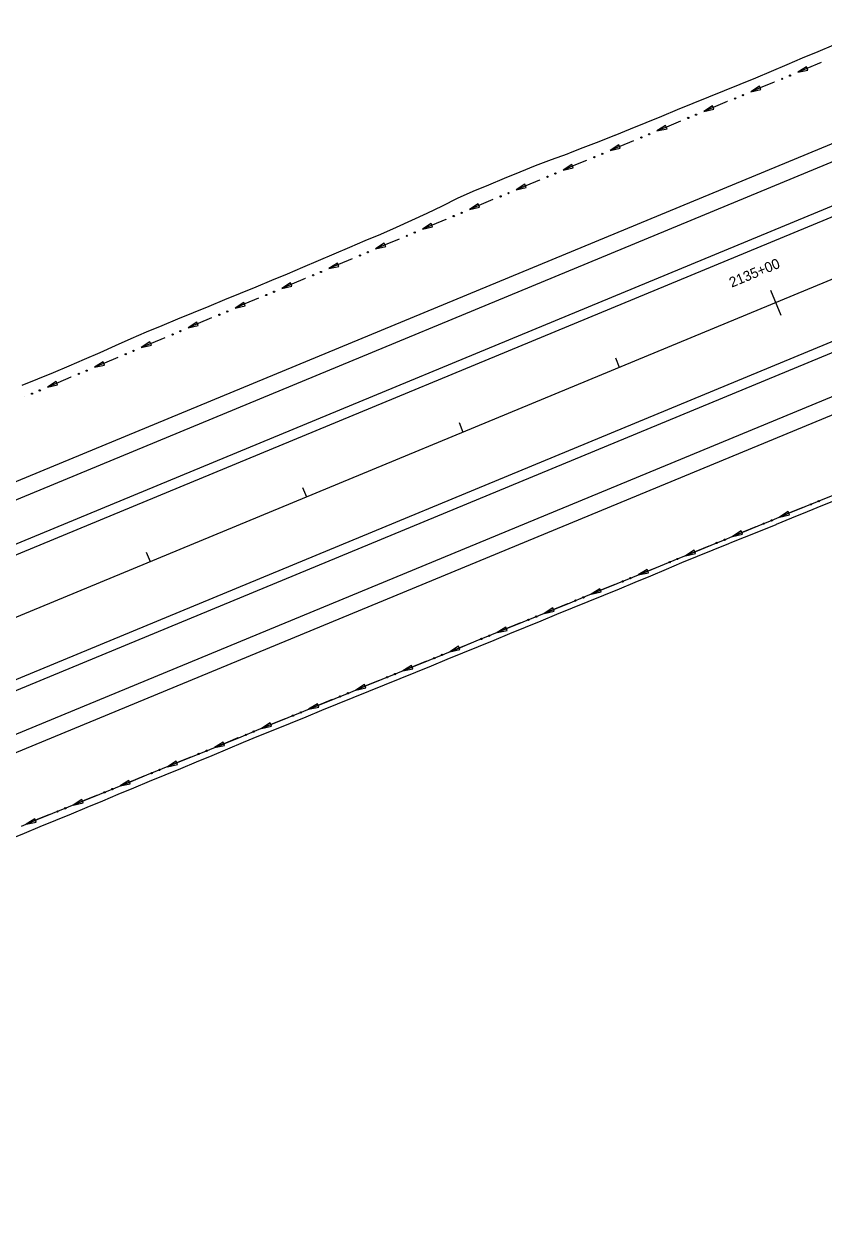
# Model space of a CAD drawing. Extents: x 1611108 to 1749517, y 619561 to 797725.
# Drawn here: x 1719028 to 1719500, y 766660 to 767372 of the extents above; entities that cross this region are included whole.
import ezdxf

# ---------------------------------------------------------------- set-up
doc = ezdxf.new("R2010")
doc.units = 0
for name, color, linetype in [('R_Ditch', 7, 'Continuous'), ('R_Horz Alg', 7, 'Continuous'), ('R_Horz Alg Stationing', 7, 'Continuous'), ('R_Proposed Const Limits', 7, 'Continuous'), ('R_Proposed Road', 7, 'Continuous')]:
    doc.layers.add(name, color=color, linetype=linetype)

msp = doc.modelspace()

# ---------------------------------------------------------------- linework, layer by layer
at = {"layer": 'R_Ditch'}
for p, q in [((1719489.75, 767346.92), (1719484.62, 767343.64)), ((1719490.56, 767344.96), (1719489.75, 767346.92)), ((1719484.62, 767343.64), (1719490.56, 767344.96)), ((1719462.02, 767335.38), (1719456.88, 767332.1)), ((1719456.88, 767332.1), (1719462.83, 767333.43)), ((1719462.83, 767333.43), (1719462.02, 767335.38)), ((1719434.29, 767323.83), (1719429.16, 767320.55)), ((1719429.16, 767320.55), (1719435.1, 767321.88)), ((1719435.1, 767321.88), (1719434.29, 767323.83)), ((1719406.56, 767312.27), (1719401.43, 767308.98)), ((1719407.38, 767310.32), (1719406.56, 767312.27)), ((1719401.43, 767308.98), (1719407.38, 767310.32)), ((1719378.85, 767300.69), (1719373.72, 767297.4)), ((1719373.72, 767297.4), (1719379.66, 767298.74)), ((1719379.66, 767298.74), (1719378.85, 767300.69)), ((1719351.14, 767289.09), (1719346.01, 767285.8)), ((1719346.01, 767285.8), (1719351.95, 767287.14)), ((1719351.95, 767287.14), (1719351.14, 767289.09)), ((1719323.43, 767277.49), (1719318.31, 767274.19)), ((1719318.31, 767274.19), (1719324.25, 767275.53)), ((1719324.25, 767275.53), (1719323.43, 767277.49)), ((1719295.73, 767265.86), (1719290.61, 767262.56)), ((1719290.61, 767262.56), (1719296.55, 767263.91)), ((1719296.55, 767263.91), (1719295.73, 767265.86)), ((1719268.04, 767254.22), (1719262.92, 767250.92)), ((1719268.86, 767252.27), (1719268.04, 767254.22)), ((1719262.92, 767250.92), (1719268.86, 767252.27)), ((1719240.36, 767242.57), (1719235.24, 767239.26)), ((1719235.24, 767239.26), (1719241.18, 767240.62)), ((1719241.18, 767240.62), (1719240.36, 767242.57)), ((1719212.67, 767230.91), (1719207.55, 767227.6)), ((1719207.55, 767227.6), (1719213.49, 767228.96)), ((1719213.49, 767228.96), (1719212.67, 767230.91)), ((1719184.99, 767219.25), (1719179.87, 767215.94)), ((1719185.81, 767217.3), (1719184.99, 767219.25)), ((1719179.87, 767215.94), (1719185.81, 767217.3)), ((1719157.31, 767207.58), (1719152.19, 767204.28)), ((1719152.19, 767204.28), (1719158.13, 767205.63)), ((1719158.13, 767205.63), (1719157.31, 767207.58)), ((1719129.63, 767195.92), (1719124.51, 767192.62)), ((1719124.51, 767192.62), (1719130.45, 767193.97)), ((1719130.45, 767193.97), (1719129.63, 767195.92)), ((1719101.95, 767184.26), (1719096.83, 767180.96)), ((1719102.77, 767182.31), (1719101.95, 767184.26)), ((1719096.83, 767180.96), (1719102.77, 767182.31)), ((1719074.26, 767172.6), (1719069.14, 767169.3)), ((1719069.14, 767169.3), (1719075.08, 767170.65)), ((1719075.08, 767170.65), (1719074.26, 767172.6)), ((1719046.58, 767160.94), (1719041.46, 767157.63)), ((1719041.46, 767157.63), (1719047.4, 767158.99)), ((1719047.4, 767158.99), (1719046.58, 767160.94)), ((1719478.94, 767083.98), (1719473.79, 767080.72)), ((1719479.74, 767082.02), (1719478.94, 767083.98)), ((1719473.79, 767080.72), (1719479.74, 767082.02)), ((1719451.15, 767072.58), (1719446, 767069.33)), ((1719446, 767069.33), (1719451.95, 767070.62)), ((1719451.95, 767070.62), (1719451.15, 767072.58)), ((1719423.35, 767061.2), (1719418.2, 767057.94)), ((1719418.2, 767057.94), (1719424.15, 767059.24)), ((1719424.15, 767059.24), (1719423.35, 767061.2)), ((1719395.55, 767049.83), (1719390.39, 767046.58)), ((1719390.39, 767046.58), (1719396.35, 767047.87)), ((1719396.35, 767047.87), (1719395.55, 767049.83)), ((1719367.74, 767038.47), (1719362.58, 767035.22)), ((1719362.58, 767035.22), (1719368.54, 767036.51)), ((1719368.54, 767036.51), (1719367.74, 767038.47)), ((1719339.93, 767027.13), (1719334.77, 767023.89)), ((1719340.72, 767025.17), (1719339.93, 767027.13)), ((1719334.77, 767023.89), (1719340.72, 767025.17)), ((1719312.11, 767015.8), (1719306.95, 767012.56)), ((1719306.95, 767012.56), (1719312.9, 767013.84)), ((1719312.9, 767013.84), (1719312.11, 767015.8)), ((1719284.29, 767004.47), (1719279.13, 767001.23)), ((1719279.13, 767001.23), (1719285.08, 767002.51)), ((1719285.08, 767002.51), (1719284.29, 767004.47)), ((1719256.47, 766993.14), (1719251.31, 766989.9)), ((1719251.31, 766989.9), (1719257.26, 766991.18)), ((1719257.26, 766991.18), (1719256.47, 766993.14)), ((1719228.65, 766981.82), (1719223.49, 766978.57)), ((1719223.49, 766978.57), (1719229.44, 766979.86)), ((1719229.44, 766979.86), (1719228.65, 766981.82)), ((1719200.83, 766970.49), (1719195.67, 766967.24)), ((1719201.62, 766968.53), (1719200.83, 766970.49)), ((1719195.67, 766967.24), (1719201.62, 766968.53)), ((1719173.01, 766959.16), (1719167.85, 766955.92)), ((1719167.85, 766955.92), (1719173.8, 766957.2)), ((1719173.8, 766957.2), (1719173.01, 766959.16)), ((1719145.19, 766947.83), (1719140.03, 766944.59)), ((1719145.98, 766945.87), (1719145.19, 766947.83)), ((1719140.03, 766944.59), (1719145.98, 766945.87)), ((1719117.37, 766936.5), (1719112.21, 766933.26)), ((1719112.21, 766933.26), (1719118.16, 766934.54)), ((1719118.16, 766934.54), (1719117.37, 766936.5)), ((1719089.55, 766925.17), (1719084.39, 766921.93)), ((1719084.39, 766921.93), (1719090.34, 766923.21)), ((1719090.34, 766923.21), (1719089.55, 766925.17)), ((1719061.73, 766913.84), (1719056.57, 766910.6)), ((1719062.52, 766911.89), (1719061.73, 766913.84)), ((1719056.57, 766910.6), (1719062.52, 766911.89)), ((1719033.91, 766902.52), (1719028.75, 766899.27)), ((1719028.75, 766899.27), (1719034.7, 766900.56)), ((1719034.7, 766900.56), (1719033.91, 766902.52))]:
    msp.add_line(p, q, dxfattribs=at)
for points in [[(1719498.47, 767349.39), (1719490.06, 767345.9), (1719484.62, 767343.64)], [(1719498.5, 767349.41), (1719498.47, 767349.39)], [(1719470.73, 767337.86), (1719462.36, 767334.38), (1719456.88, 767332.1)], [(1719470.77, 767337.88), (1719470.73, 767337.86)], [(1719443, 767326.32), (1719434.67, 767322.84), (1719429.16, 767320.55)], [(1719443.04, 767326.33), (1719443, 767326.32)], [(1719415.28, 767314.76), (1719406.98, 767311.3), (1719401.43, 767308.98)], [(1719415.31, 767314.77), (1719415.28, 767314.76)], [(1719387.56, 767303.18), (1719379.55, 767299.84), (1719379.3, 767299.73), (1719373.72, 767297.4)], [(1719387.59, 767303.2), (1719387.56, 767303.18)], [(1719359.85, 767291.59), (1719353.3, 767288.86), (1719351.62, 767288.15), (1719346.01, 767285.8)], [(1719359.88, 767291.61), (1719359.85, 767291.59)], [(1719332.14, 767279.99), (1719323.95, 767276.56), (1719318.31, 767274.19)], [(1719332.18, 767280), (1719332.14, 767279.99)], [(1719304.44, 767268.37), (1719296.29, 767264.95), (1719290.61, 767262.56)], [(1719304.48, 767268.39), (1719304.44, 767268.37)], [(1719276.75, 767256.74), (1719268.63, 767253.32), (1719262.92, 767250.92)], [(1719276.78, 767256.75), (1719276.75, 767256.74)], [(1719249.06, 767245.09), (1719240.98, 767241.68), (1719235.24, 767239.26)], [(1719249.1, 767245.1), (1719249.06, 767245.09)], [(1719221.38, 767233.43), (1719213.34, 767230.04), (1719207.55, 767227.6)], [(1719221.41, 767233.44), (1719221.38, 767233.43)], [(1719193.7, 767221.76), (1719185.69, 767218.39), (1719179.87, 767215.94)], [(1719193.73, 767221.78), (1719193.7, 767221.76)], [(1719166.01, 767210.1), (1719158.04, 767206.74), (1719152.19, 767204.28)], [(1719166.05, 767210.12), (1719166.01, 767210.1)], [(1719138.33, 767198.44), (1719130.39, 767195.1), (1719124.51, 767192.62)], [(1719138.37, 767198.46), (1719138.33, 767198.44)], [(1719110.65, 767186.78), (1719102.75, 767183.45), (1719096.83, 767180.96)], [(1719110.68, 767186.8), (1719110.65, 767186.78)], [(1719082.97, 767175.12), (1719075.1, 767171.8), (1719069.14, 767169.3)], [(1719083, 767175.13), (1719082.97, 767175.12)], [(1719055.29, 767163.46), (1719047.45, 767160.16), (1719041.46, 767157.63)], [(1719055.32, 767163.47), (1719055.29, 767163.46)], [(1719027.64, 767151.81), (1719027.6, 767151.8)], [(1719026.08, 766898.19), (1719035.34, 766901.96), (1719044.6, 766905.73), (1719053.86, 766909.5), (1719063.12, 766913.27), (1719072.38, 766917.04), (1719081.65, 766920.81), (1719090.91, 766924.59), (1719100.17, 766928.36), (1719109.43, 766932.13), (1719118.69, 766935.9), (1719127.96, 766939.67), (1719137.22, 766943.44), (1719146.48, 766947.21), (1719155.74, 766950.98), (1719165, 766954.76), (1719174.26, 766958.53), (1719183.53, 766962.3), (1719192.79, 766966.07), (1719202.05, 766969.84), (1719211.31, 766973.61), (1719220.57, 766977.39), (1719229.83, 766981.16), (1719239.1, 766984.93), (1719248.36, 766988.7), (1719257.62, 766992.47), (1719266.88, 766996.24), (1719276.14, 767000.01), (1719285.41, 767003.79), (1719294.67, 767007.56), (1719303.93, 767011.33), (1719313.19, 767015.1), (1719322.45, 767018.87), (1719331.71, 767022.64), (1719340.98, 767026.41), (1719350.24, 767030.19), (1719359.5, 767033.96), (1719368.76, 767037.74), (1719378.01, 767041.52), (1719387.27, 767045.3), (1719396.53, 767049.08), (1719405.79, 767052.87), (1719415.04, 767056.65), (1719424.3, 767060.44), (1719433.55, 767064.23), (1719442.8, 767068.02), (1719444.49, 767068.71), (1719452.06, 767071.81), (1719461.31, 767075.6), (1719470.56, 767079.4), (1719470.81, 767079.5), (1719479.81, 767083.2), (1719489.06, 767087), (1719498.31, 767090.8), (1719507.56, 767094.6)], [(1719487.66, 767086.42), (1719479.81, 767083.2), (1719473.79, 767080.72)], [(1719487.7, 767086.44), (1719487.66, 767086.42)], [(1719459.88, 767075.02), (1719452.06, 767071.81), (1719446, 767069.33)], [(1719459.91, 767075.03), (1719459.88, 767075.02)], [(1719432.08, 767063.63), (1719424.3, 767060.44), (1719418.2, 767057.94)], [(1719432.12, 767063.64), (1719432.08, 767063.63)], [(1719404.28, 767052.25), (1719396.53, 767049.08), (1719390.39, 767046.58)], [(1719404.32, 767052.26), (1719404.28, 767052.25)], [(1719376.47, 767040.89), (1719368.76, 767037.74), (1719362.58, 767035.22)], [(1719376.51, 767040.91), (1719376.47, 767040.89)], [(1719348.66, 767029.55), (1719340.98, 767026.41), (1719334.77, 767023.89)], [(1719348.69, 767029.56), (1719348.66, 767029.55)], [(1719320.84, 767018.21), (1719313.19, 767015.1), (1719306.95, 767012.56)], [(1719320.88, 767018.23), (1719320.84, 767018.21)], [(1719293.02, 767006.89), (1719285.41, 767003.79), (1719279.13, 767001.23)], [(1719293.06, 767006.9), (1719293.02, 767006.89)], [(1719265.2, 766995.56), (1719257.62, 766992.47), (1719251.31, 766989.9)], [(1719265.24, 766995.57), (1719265.2, 766995.56)], [(1719237.38, 766984.23), (1719229.83, 766981.16), (1719223.49, 766978.57)], [(1719237.42, 766984.24), (1719237.38, 766984.23)], [(1719209.56, 766972.9), (1719202.05, 766969.84), (1719195.67, 766967.24)], [(1719209.6, 766972.92), (1719209.56, 766972.9)], [(1719181.74, 766961.57), (1719174.26, 766958.53), (1719167.85, 766955.92)], [(1719181.78, 766961.59), (1719181.74, 766961.57)], [(1719153.92, 766950.24), (1719146.48, 766947.21), (1719140.03, 766944.59)], [(1719153.96, 766950.26), (1719153.92, 766950.24)], [(1719126.1, 766938.92), (1719118.69, 766935.9), (1719112.21, 766933.26)], [(1719126.14, 766938.93), (1719126.1, 766938.92)], [(1719098.28, 766927.59), (1719090.91, 766924.59), (1719084.39, 766921.93)], [(1719098.32, 766927.6), (1719098.28, 766927.59)], [(1719070.46, 766916.26), (1719063.12, 766913.27), (1719056.57, 766910.6)], [(1719070.5, 766916.27), (1719070.46, 766916.26)], [(1719042.64, 766904.93), (1719035.34, 766901.96), (1719028.75, 766899.27)], [(1719042.68, 766904.95), (1719042.64, 766904.93)]]:
    msp.add_lwpolyline(points, dxfattribs=at)
for centre in [(1719475.38, 767339.76), (1719480.01, 767341.68), (1719447.65, 767328.22), (1719452.28, 767330.14), (1719424.55, 767318.59), (1719419.93, 767316.66), (1719392.21, 767305.09), (1719396.83, 767307.02), (1719364.49, 767293.5), (1719369.11, 767295.43), (1719336.79, 767281.9), (1719341.41, 767283.83), (1719309.09, 767270.28), (1719313.71, 767272.22), (1719286.01, 767260.59), (1719281.39, 767258.65), (1719253.7, 767247), (1719258.32, 767248.95), (1719226.02, 767235.34), (1719230.64, 767237.29), (1719202.96, 767225.63), (1719198.34, 767223.68), (1719170.66, 767212.02), (1719175.27, 767213.96), (1719142.97, 767200.36), (1719147.59, 767202.3), (1719119.91, 767190.64), (1719115.29, 767188.7), (1719087.61, 767177.04), (1719092.23, 767178.98), (1719059.93, 767165.37), (1719064.55, 767167.32), (1719032.25, 767153.71), (1719036.86, 767155.66), (1719496.96, 767090.2), (1719492.32, 767088.3), (1719464.54, 767076.89), (1719469.17, 767078.79), (1719436.74, 767065.5), (1719441.38, 767067.4), (1719408.94, 767054.12), (1719413.58, 767056.01), (1719381.14, 767042.76), (1719385.77, 767044.65), (1719357.96, 767033.3), (1719353.32, 767031.41), (1719325.51, 767020.08), (1719330.15, 767021.96), (1719297.69, 767008.75), (1719302.33, 767010.64), (1719269.87, 766997.42), (1719274.51, 766999.31), (1719242.05, 766986.09), (1719246.69, 766987.98), (1719218.87, 766976.65), (1719214.23, 766974.76), (1719186.41, 766963.43), (1719191.05, 766965.32), (1719158.59, 766952.1), (1719163.23, 766953.99), (1719130.77, 766940.78), (1719135.41, 766942.67), (1719102.95, 766929.45), (1719107.59, 766931.34), (1719079.77, 766920.01), (1719075.13, 766918.12), (1719047.31, 766906.79), (1719051.95, 766908.68)]:
    msp.add_circle(centre, 0.375, dxfattribs=at)
at = {"layer": 'R_Horz Alg'}
msp.add_line((1715964.86, 765755.05), (1723860.62, 769025.58), dxfattribs=at)
at = {"layer": 'R_Horz Alg Stationing'}
for points in [[(1719468.52, 767214.98), (1719474.65, 767200.2)], [(1719376.9, 767174.86), (1719379.2, 767169.32)], [(1719284.51, 767136.59), (1719286.81, 767131.05)], [(1719192.13, 767098.32), (1719194.42, 767092.78)], [(1719099.74, 767060.06), (1719102.03, 767054.51)]]:
    msp.add_lwpolyline(points, dxfattribs=at)
at = {"layer": 'R_Proposed Const Limits'}
for points in [[(1719026.41, 767158.69), (1719035.67, 767162.47), (1719044.92, 767166.26), (1719054.13, 767170.16), (1719063.32, 767174.1), (1719072.51, 767178.05), (1719081.62, 767182.19), (1719090.77, 767186.22), (1719099.95, 767190.2), (1719109.17, 767194.08), (1719118.4, 767197.93), (1719127.65, 767201.72), (1719136.91, 767205.51), (1719146.16, 767209.29), (1719155.4, 767213.12), (1719164.64, 767216.95), (1719173.87, 767220.79), (1719183.11, 767224.62), (1719192.34, 767228.46), (1719201.54, 767232.39), (1719210.74, 767236.31), (1719219.94, 767240.23), (1719229.14, 767244.14), (1719238.34, 767248.05), (1719247.48, 767252.13), (1719256.64, 767256.16), (1719265.72, 767260.36), (1719274.77, 767264.64), (1719283.7, 767269.22), (1719292.82, 767273.32), (1719302.06, 767277.16), (1719311.29, 767281), (1719320.53, 767284.82), (1719329.78, 767288.61), (1719339.17, 767292.08), (1719348.57, 767295.53), (1719350.28, 767296.16), (1719357.86, 767299.21), (1719367.24, 767302.71), (1719376.5, 767306.48), (1719376.75, 767306.58), (1719385.79, 767310.2), (1719395.04, 767313.98), (1719404.3, 767317.77), (1719413.55, 767321.56), (1719422.81, 767325.35), (1719432.08, 767329.09), (1719441.36, 767332.83), (1719450.63, 767336.57), (1719459.85, 767340.44), (1719469.06, 767344.34), (1719478.27, 767348.24), (1719487.48, 767352.13), (1719496.7, 767356.01), (1719505.95, 767359.8)], [(1719018.54, 766890.25), (1719027.79, 766894.04), (1719037.05, 766897.83), (1719046.3, 766901.62), (1719055.56, 766905.41), (1719064.79, 766909.25), (1719074.01, 766913.11), (1719083.24, 766916.97), (1719092.48, 766920.8), (1719101.72, 766924.62), (1719110.96, 766928.44), (1719120.2, 766932.27), (1719129.44, 766936.09), (1719138.67, 766939.94), (1719147.89, 766943.81), (1719157.11, 766947.67), (1719166.35, 766951.51), (1719175.61, 766955.27), (1719184.88, 766959.03), (1719194.15, 766962.79), (1719203.41, 766966.57), (1719212.67, 766970.34), (1719221.93, 766974.11), (1719231.19, 766977.89), (1719240.45, 766981.66), (1719249.72, 766985.4), (1719258.99, 766989.16), (1719268.26, 766992.92), (1719277.5, 766996.74), (1719286.72, 767000.62), (1719295.98, 767004.38), (1719305.26, 767008.12), (1719314.51, 767011.91), (1719323.77, 767015.69), (1719333.03, 767019.48), (1719342.26, 767023.31), (1719351.5, 767027.15), (1719360.76, 767030.9), (1719370.03, 767034.66), (1719379.3, 767038.42), (1719388.53, 767042.27), (1719397.75, 767046.14), (1719406.97, 767050), (1719416.19, 767053.87), (1719425.43, 767057.7), (1719434.68, 767061.5), (1719443.95, 767065.25), (1719445.64, 767065.93), (1719453.23, 767068.99), (1719462.51, 767072.72), (1719471.78, 767076.46), (1719472.03, 767076.56), (1719481.04, 767080.25), (1719490.29, 767084.04), (1719499.51, 767087.91), (1719508.8, 767091.61)]]:
    msp.add_lwpolyline(points, dxfattribs=at)
at = {"layer": 'R_Proposed Road'}
for p, q in [((1715936.54, 765823.42), (1723832.3, 769093.95)), ((1715940.37, 765814.18), (1723836.12, 769084.71)), ((1715949.55, 765792.01), (1723845.31, 769062.54)), ((1715951.85, 765786.47), (1723847.6, 769056.99)), ((1715977.87, 765723.64), (1723873.63, 768994.17)), ((1715980.17, 765718.1), (1723875.92, 768988.63)), ((1715989.35, 765695.93), (1723885.11, 768966.45)), ((1715993.18, 765686.69), (1723888.93, 768957.22))]:
    msp.add_line(p, q, dxfattribs=at)

# ---------------------------------------------------------------- texts
at = {"layer": 'R_Horz Alg Stationing'}
msp.add_text('2135+00', height=6, rotation=22.5, dxfattribs=at).set_placement((1719445.62, 767216.32))

doc.saveas('drawing.dxf')
